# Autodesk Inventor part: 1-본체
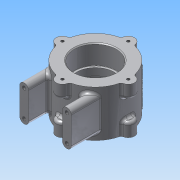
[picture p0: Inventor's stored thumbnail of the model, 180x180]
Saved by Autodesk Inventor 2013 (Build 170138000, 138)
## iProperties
Created: 2015-03
Part Number: 1-본체
Material: 알루미늄 6061
Document SubType Name: Modeling
Designer: ST5
Density: 2.71 g/cm^3
Mass: 450.777 g
Surface Area: 332.735 cm^2
Volume: 166.339 cm^3
Author: ST5
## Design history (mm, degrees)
sketch "스케치1"
  geometry: C1 r 37 at (0, 0); 1 further point
  constraints: 1 centre point, 1 coincident
  dimensions: "d0" = 74 diameter of C1
extrude "돌출1" new body sketch "스케치1" stored distance "d2" = 52; taper "d3" = 0 deg
sketch "스케치2"
  geometry: C1 r 37 at (0, 0) reference; C2 r 23.5 at (0, 0)
  constraints: 1 centre point, 1 coincident
  dimensions: "d4" = 47 diameter of C2
extrude "돌출2" cut sketch "스케치2" distance "d6" = 22; taper "d7" = 0 deg
sketch "스케치3"
  geometry: C1 r 37 at (0, 0) reference; C2 r 23.5 at (0, 0)
  constraints: 1 centre point, 1 coincident
  dimensions: "d8" = 47 diameter of C2
extrude "돌출3" cut sketch "스케치3" distance "d10" = 22; taper "d11" = 0 deg
sketch "스케치4"
  geometry: C1 r 23.5 at (0, 0) reference; C2 r 21 at (0, 0)
  constraints: 1 centre point, 1 coincident
  dimensions: "d12" = 42 diameter of C2
extrude "돌출4" cut sketch "스케치4" stored distance "d14" = 0; taper "d15" = 0 deg
sketch "스케치5"
  geometry: C1 r 23.5 at (0, 0) reference; C2 r 7 at (0, 37); C3 r 7 at (-37, 0); C4 r 7 at (37, 0); C5 r 7 at (0, -37); A1 r 37 centre (0, 0) between (0, 37) and (-37, 0) reference
  constraints: 4 centre point, 4 point on circle, 3 equal radius, 2 horizontal alignment, 2 vertical alignment
  dimensions: "d16" = 14 diameter of C2
extrude "돌출5" join sketch "스케치5" distance "d18" = 15; taper "d19" = 0 deg
sketch "스케치6"
  geometry: A1 r 7 centre (37, 0) between (36.338, -6.969) and (36.338, 6.969) reference; A2 r 7 centre (0, 37) between (6.969, 36.338) and (-6.969, 36.338) reference; A3 r 7 centre (-37, 0) between (-36.338, 6.969) and (-36.338, -6.969) reference; A4 r 7 centre (0, -37) between (-6.969, -36.338) and (6.969, -36.338) reference; 4 further points
  constraints: 4 coincident
hole "구멍1" sketch "스케치6" at (0, 37), (-37, 0), (0, -37), (37, 0) diameter "d20" = 3.242; stored, may be unused: countersink angle "d24" = 90 deg, drill point angle "d26" = 118 deg; dims "d21" = 8, "d22" = 4, "d23" = 2, "d25" = 11
node "작업 평면1"
sketch "스케치7"
  geometry: L1 (19, 15)-(19, -15); L2 (29, 15)-(29, -15); A1 r 5 centre (24, 15) between (19, 15) and (29, 15); A2 r 5 centre (24, -15) between (19, -15) and (29, -15); 2 further points
  constraints: 4 end point, 4 point on circle, 2 centre point, 2 tangent, 1 equal radius, 1 horizontal alignment, 1 midpoint, 1 parallel, 1 vertical, 1 vertical alignment
  dimensions: "d28" = 10 diameter of A1; "d30" = 40 dimension on A1 A2; "d31" = 24 horizontal distance of A2.centre point (0, 0)
extrude "돌출6" join sketch "스케치7" stored distance "d32" = 0; taper "d33" = 0 deg
sketch "스케치8"
  geometry: L1 (-29, -15)-(-29, 15) reference; L2 (-19, 15)-(-19, -15) reference; A1 r 5 centre (24, 15) between (29, 15) and (19, 15) reference; A2 r 5 centre (24, -15) between (19, -15) and (29, -15) reference; A3 r 5 centre (-24, 15) between (-19, 15) and (-29, 15) reference; A4 r 5 centre (-24, -15) between (-29, -15) and (-19, -15) reference; 5 further points
  constraints: 4 coincident
hole "구멍2" sketch "스케치8" at (24, 15), (24, -15), (-24, 15), (-24, -15) diameter "d34" = 4.134; stored, may be unused: countersink angle "d38" = 90 deg, drill point angle "d40" = 118 deg; dims "d35" = 6, "d36" = 4, "d37" = 2, "d39" = 8
fillet "모깎기1" dims "d41" = 0.3
chamfer "모따기1" distance "d42" = 1; stored, may be unused: second distance "d43" = 2, angle "d44" = 45 deg
chamfer "모따기2" distance "d45" = 1; stored, may be unused: second distance "d46" = 2, angle "d47" = 45 deg
fillet "모깎기2" dims "d48" = 3
fillet "모깎기3" dims "d49" = 3
fillet "모깎기4" dims "d50" = 3
node "작업 평면3"
  node "작업 평면2"
sketch "스케치9"
  geometry: L1 (18.921, 26)-(-18.921, 26) reference; 2 further points
  constraints: 1 coincident, 1 other
  dimensions: "d52" = 26 distance from line of L1 point (0, 0)
feature "엠보싱1" sketch "스케치9" dims "d53" = 0.5, "d54" = 0
node "솔리드1"
mirror "대칭1"
mirror "대칭2"
mirror "대칭3"
node "투영된 루프1"
other parameters: "d27" = -56, "d51" = 45 deg
